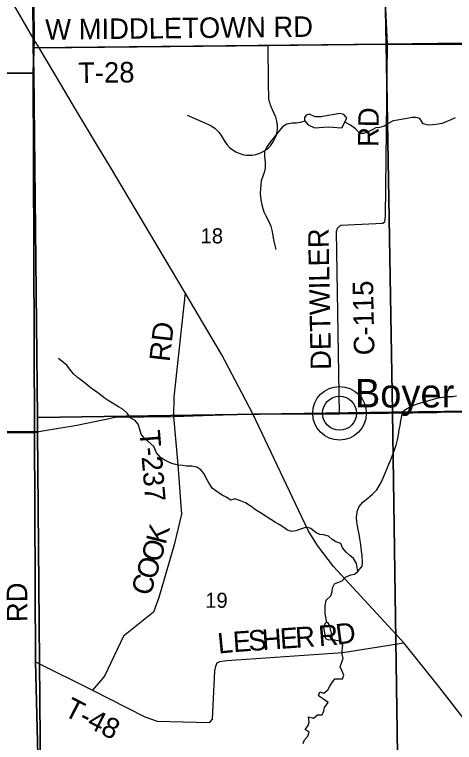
# Model space of a CAD drawing. Extents: x 0 to 36.9, y 0 to 22.
# Drawn here: x 4.166 to 5.386, y 16.582 to 18.601 of the extents above; entities that cross this region are included whole.
import ezdxf

# ---------------------------------------------------------------- set-up
doc = ezdxf.new("R2010")
doc.units = 0
for name, color, linetype in [('GM_X_County_Road', 7, 'Continuous'), ('GM_X_County_Road_Text', 7, 'Continuous'), ('GM_X_Minor_Lake', 7, 'Continuous'), ('GM_X_Minor_River', 7, 'Continuous'), ('GM_X_Rail_Line', 7, 'Continuous'), ('GM_X_Section', 7, 'Continuous'), ('GM_X_Section_Text', 7, 'Continuous'), ('GM_X_State_Route', 7, 'Continuous'), ('GM_X_Township_Road', 7, 'Continuous'), ('GM_X_Township_Road_Text', 7, 'Continuous'), ('GM_X_Unincorporated', 7, 'Continuous'), ('GM_X_Unincorporated_Location', 7, 'Continuous'), ('GM_X_Unincorporated_Text', 7, 'Continuous')]:
    doc.layers.add(name, color=color, linetype=linetype)

msp = doc.modelspace()

# ---------------------------------------------------------------- linework, layer by layer
at = {"layer": 'GM_X_County_Road'}
for points in [[(5.0673, 17.4931), (5.0594, 17.9986), (5.0622, 18.0085), (5.0708, 18.0163), (5.188, 18.0224), (5.1928, 18.0266), (5.1952, 18.0408), (5.2008, 18.5186), (5.1771, 19.01), (5.1803, 19.5234)], [(4.2216, 17.4415), (4.2176, 18.4377), (4.2202, 18.5304)], [(4.2488, 15.4651), (4.2434, 15.9526), (4.243, 16.0644), (4.2239, 16.8055), (4.2216, 17.4415)]]:
    msp.add_lwpolyline(points, dxfattribs=at)
at = {"layer": 'GM_X_Minor_Lake'}
for points in [[(5.0874, 18.3132), (5.0846, 18.3166), (5.0792, 18.3233), (5.0681, 18.3262), (5.0154, 18.3166), (4.9998, 18.3171), (4.9845, 18.324), (4.975, 18.3216), (4.9698, 18.3151), (4.9707, 18.3067), (4.9804, 18.2951), (4.9984, 18.2867), (5.036, 18.2896), (5.0741, 18.2864)], [(5.0741, 18.2864), (5.0874, 18.3132)], [(5.04, 16.9072), (5.0349, 16.9143), (5.0292, 16.9139), (5.027, 16.9112), (5.0229, 16.902), (5.0288, 16.8702), (5.0364, 16.8661), (5.0463, 16.8671), (5.0474, 16.8776)], [(5.0474, 16.8776), (5.04, 16.9072)]]:
    msp.add_lwpolyline(points, dxfattribs=at)
at = {"layer": 'GM_X_Minor_River'}
for points in [[(5.3881, 18.3144), (5.3745, 18.308), (5.3647, 18.3045), (5.3519, 18.2989), (5.336, 18.296), (5.3265, 18.295), (5.314, 18.2941), (5.2999, 18.2972), (5.2898, 18.3122), (5.2802, 18.3155), (5.2685, 18.3149), (5.2552, 18.3128), (5.2385, 18.3098), (5.2283, 18.3081), (5.2158, 18.3056), (5.2027, 18.2989)], [(4.9717, 18.3054), (4.9585, 18.301), (4.9479, 18.2997), (4.9357, 18.2991), (4.9217, 18.297), (4.9089, 18.2891), (4.8974, 18.2741), (4.887, 18.2618), (4.8748, 18.2464), (4.8655, 18.2337), (4.8597, 18.2211), (4.8591, 18.2066), (4.8613, 18.1903), (4.8609, 18.1744), (4.858, 18.163), (4.8544, 18.1523), (4.8505, 18.14), (4.8488, 18.1282), (4.8478, 18.1187), (4.8473, 18.1032), (4.8488, 18.0872), (4.8525, 18.0695), (4.8573, 18.0532), (4.8629, 18.0423), (4.8683, 18.0325), (4.8767, 18.0137), (4.8795, 18.0028), (4.8824, 17.988), (4.8842, 17.9759), (4.887, 17.9638), (4.8904, 17.949)], [(5.2027, 18.2989), (5.1925, 18.2915), (5.1782, 18.2878), (5.168, 18.2861), (5.1582, 18.281), (5.1446, 18.2747), (5.1341, 18.2707), (5.1234, 18.2709), (5.1122, 18.284), (5.0983, 18.2936), (5.0819, 18.3021)], [(5.1183, 17.0563), (5.1141, 17.0786), (5.1059, 17.0918), (5.0963, 17.1), (5.0862, 17.1097), (5.0758, 17.122), (5.0706, 17.1337), (5.0576, 17.138), (5.0469, 17.1446), (5.0368, 17.154), (5.0231, 17.1579), (5.0132, 17.1585), (5.0025, 17.1632), (4.9882, 17.1751), (4.9756, 17.1794), (4.959, 17.1738), (4.9458, 17.169), (4.9352, 17.167), (4.9234, 17.1709), (4.9103, 17.1802), (4.8999, 17.1868), (4.8899, 17.1923), (4.8765, 17.2005), (4.8642, 17.2086), (4.8481, 17.2186), (4.8339, 17.2274), (4.8219, 17.2363), (4.8062, 17.2463), (4.7928, 17.2521), (4.7771, 17.2579), (4.7658, 17.2543), (4.7527, 17.262), (4.7416, 17.2679), (4.7247, 17.2794), (4.7143, 17.2876), (4.7038, 17.3037), (4.6967, 17.3169), (4.692, 17.327), (4.6826, 17.3379), (4.6719, 17.3453), (4.6574, 17.3481), (4.6441, 17.3486), (4.6315, 17.3499), (4.6209, 17.3512), (4.6091, 17.3536), (4.5995, 17.3565), (4.5808, 17.3653), (4.5708, 17.3723), (4.5595, 17.385), (4.5524, 17.4024), (4.5358, 17.4177), (4.5262, 17.4247), (4.5172, 17.4371), (4.5135, 17.4499), (4.5084, 17.4642), (4.5002, 17.4751), (4.4887, 17.4814), (4.4786, 17.4952), (4.467, 17.5049), (4.4543, 17.5126), (4.4374, 17.523), (4.4255, 17.53), (4.4144, 17.5378), (4.404, 17.5463), (4.3928, 17.5545), (4.3832, 17.5611), (4.3736, 17.5682), (4.3624, 17.5775), (4.3504, 17.5871), (4.3408, 17.5942), (4.3293, 17.6042), (4.3215, 17.6147), (4.3106, 17.6285), (4.2979, 17.6386), (4.2882, 17.6464)], [(5.0322, 16.9141), (5.0278, 16.9393), (5.0274, 16.962), (5.0306, 16.9761), (5.0436, 16.9889), (5.0472, 16.9992), (5.0482, 17.011), (5.0533, 17.0221), (5.0631, 17.0257), (5.0748, 17.0301), (5.0837, 17.0405), (5.0988, 17.0465), (5.1086, 17.0485), (5.1183, 17.0563), (5.1299, 17.0709), (5.1316, 17.0805), (5.1301, 17.1002), (5.1287, 17.1127), (5.1274, 17.1225), (5.1253, 17.1362), (5.1235, 17.1471), (5.1218, 17.16), (5.1193, 17.1721), (5.1172, 17.1831), (5.1159, 17.1941), (5.1149, 17.2055), (5.1155, 17.215), (5.1172, 17.2249), (5.1219, 17.236), (5.1323, 17.2487), (5.1462, 17.2596), (5.1585, 17.2704), (5.1705, 17.2824), (5.1775, 17.2932), (5.1837, 17.3043), (5.1896, 17.318), (5.1943, 17.3288), (5.1986, 17.3402), (5.2041, 17.3536), (5.2088, 17.3643), (5.2147, 17.3785), (5.2194, 17.3911), (5.2248, 17.4068), (5.2279, 17.4212), (5.2307, 17.4353), (5.2331, 17.4487), (5.2356, 17.4605), (5.2376, 17.4738), (5.239, 17.4833), (5.2411, 17.4929), (5.2458, 17.5024), (5.2661, 17.5142), (5.2835, 17.521), (5.2933, 17.5238), (5.3277, 17.5343), (5.3409, 17.5379), (5.3541, 17.5397), (5.3682, 17.5411), (5.3822, 17.5417), (5.3921, 17.543)], [(4.9664, 16.579), (4.97, 16.5889), (4.9797, 16.5993), (4.9836, 16.61), (4.9721, 16.6174), (4.9807, 16.6286), (4.9835, 16.6393), (4.9817, 16.6533), (4.9951, 16.6497), (5.0067, 16.6587), (5.0196, 16.6585), (5.0243, 16.6692), (5.0257, 16.6791), (5.0357, 16.6926), (5.0226, 16.7019), (5.0095, 16.7115), (5.0128, 16.7222), (5.0238, 16.719), (5.0354, 16.7279), (5.0406, 16.7379), (5.0468, 16.7479), (5.0546, 16.7579), (5.0755, 16.7582), (5.0795, 16.7682), (5.0751, 16.7799), (5.0692, 16.7919), (5.0739, 16.8049), (5.0779, 16.8156), (5.0743, 16.8269), (5.0745, 16.838), (5.0769, 16.8513), (5.0698, 16.8626), (5.0576, 16.865), (5.0464, 16.8675)]]:
    msp.add_lwpolyline(points, dxfattribs=at)
at = {"layer": 'GM_X_Rail_Line'}
for points in [[(8.9, 14.5158), (8.9, 20.5927), (8.7004, 20.5894), (8.4791, 20.5781), (8.4706, 20.5777), (8.1451, 20.581), (7.7514, 20.5725), (7.4889, 20.5693), (7.1656, 20.5637), (7.1468, 20.5633), (6.1727, 20.5478), (5.9236, 20.5446), (5.3186, 20.5329), (5.2978, 20.5324), (5.1496, 20.5295), (4.5929, 20.5183), (4.1742, 20.5119), (4.2095, 19.5156), (4.2124, 19.4314), (4.22, 18.531), (4.2174, 18.4382), (4.2214, 17.442), (4.2237, 16.806), (4.2428, 16.065)], [(4.2428, 16.065), (4.2237, 16.806), (4.2214, 17.442), (4.2174, 18.4382), (4.22, 18.531), (4.2124, 19.4314), (4.2095, 19.5156), (4.1742, 20.5119), (3.4355, 20.4995), (3.1942, 20.4953), (2.6054, 20.4898), (2.1, 20.4802), (2.1, 14.4405)]]:
    msp.add_lwpolyline(points, dxfattribs=at)
at = {"layer": 'GM_X_Section'}
for points in [[(6.1867, 19.5319), (6.2072, 18.5313), (5.197, 18.519), (5.1777, 19.5195)], [(5.1777, 19.5195), (5.197, 18.519), (4.2176, 18.508), (4.212, 19.4289), (4.2133, 19.5112)], [(4.212, 19.4289), (4.2176, 18.508), (4.219, 18.4391), (3.226, 18.4277), (3.2188, 19.419)], [(4.2176, 18.508), (5.197, 18.519), (5.2141, 17.498), (4.2298, 17.4831), (4.219, 18.4391)], [(5.197, 18.519), (6.2072, 18.5313), (6.2201, 17.5106), (5.2141, 17.498)], [(4.219, 18.4391), (4.2298, 17.4831), (4.2298, 17.4444), (3.2373, 17.4365), (3.226, 18.4277)], [(6.2201, 17.5106), (6.226, 16.4996), (5.2292, 16.4845), (5.2141, 17.498)], [(5.2141, 17.498), (5.2292, 16.4845), (4.2381, 16.4858), (4.2298, 17.4444), (4.2298, 17.4831)], [(4.2298, 17.4444), (4.2381, 16.4858), (4.2388, 16.4513), (3.2483, 16.4396), (3.2373, 17.4365)]]:
    msp.add_lwpolyline(points, close=True, dxfattribs=at)
at = {"layer": 'GM_X_State_Route'}
for p, q in [((4.234, 18.5081), (4.2202, 18.5304)), ((4.2949, 18.4062), (4.234, 18.5081)), ((4.3354, 18.3383), (4.2949, 18.4062)), ((4.3658, 18.2874), (4.3354, 18.3383)), ((4.3962, 18.2364), (4.3658, 18.2874)), ((4.4317, 18.177), (4.3962, 18.2364))]:
    msp.add_line(p, q, dxfattribs=at)
for points in [[(4.2202, 18.5304), (4.0532, 18.8191), (4.0295, 18.8744), (3.802, 19.4268)], [(5.504, 16.4959), (5.45, 16.5871), (5.4199, 16.6383), (5.3454, 16.7333), (5.2454, 16.8581), (5.0508, 17.0699), (5.0061, 17.1277), (4.9804, 17.1698), (4.8265, 17.4934), (4.741, 17.6571), (4.6391, 17.8287), (4.4642, 18.1227), (4.4317, 18.177)], [(4.2216, 17.4415), (4.243, 17.446), (4.334, 17.4611), (4.4155, 17.4778), (4.4453, 17.4838), (4.6071, 17.4861), (4.8265, 17.4934)], [(4.8265, 17.4934), (5.0673, 17.4931), (5.3373, 17.4973), (5.3473, 17.4975)], [(5.3473, 17.4975), (5.4944, 17.4998), (5.5025, 17.4999), (5.5148, 17.5001), (5.6182, 17.5016), (5.6272, 17.5017)], [(2.4919, 17.4281), (3.2285, 17.4352), (4.2216, 17.4415)]]:
    msp.add_lwpolyline(points, dxfattribs=at)
at = {"layer": 'GM_X_Township_Road'}
msp.add_line((5.2008, 18.5186), (5.5124, 18.5192), dxfattribs=at)
for points in [[(4.234, 18.5081), (4.8692, 18.5153), (5.2008, 18.5186)], [(4.6446, 18.3215), (4.6726, 18.3093), (4.6952, 18.2997), (4.7035, 18.2961), (4.7111, 18.2923), (4.7163, 18.2891), (4.722, 18.285), (4.7263, 18.2812), (4.7323, 18.2746), (4.7388, 18.2652), (4.7471, 18.2515), (4.7548, 18.2403), (4.7618, 18.2324), (4.7696, 18.226), (4.7794, 18.2196), (4.7879, 18.2159), (4.802, 18.2117), (4.8097, 18.2109), (4.8151, 18.2107), (4.8251, 18.2109), (4.8356, 18.2126), (4.8465, 18.2163), (4.8559, 18.2209), (4.8627, 18.2253), (4.8702, 18.2312), (4.8757, 18.2368), (4.8837, 18.2474), (4.8884, 18.2567), (4.8924, 18.2671), (4.8944, 18.2766), (4.8952, 18.284), (4.8955, 18.2933), (4.8939, 18.3053), (4.8905, 18.3164), (4.8815, 18.3364), (4.8764, 18.3496), (4.8739, 18.3564), (4.8718, 18.3619), (4.8711, 18.366), (4.8705, 18.4122), (4.8692, 18.5153)], [(2.1, 18.4182), (3.2275, 18.4294), (3.5067, 18.4318), (4.2176, 18.4377)], [(4.6391, 17.8287), (4.6073, 17.5395), (4.6071, 17.4861), (4.6189, 17.3516), (4.6258, 17.2514), (4.6293, 17.2146), (4.6088, 17.1301), (4.5658, 16.9842), (4.5511, 16.9432), (4.4681, 16.8764), (4.4151, 16.7653), (4.3819, 16.7269)], [(4.2239, 16.8055), (4.3819, 16.7269), (4.5274, 16.653), (4.5615, 16.6412), (4.7056, 16.6368), (4.7097, 16.6399), (4.7149, 16.6469), (4.7213, 16.7809), (4.7244, 16.7935), (4.728, 16.8023), (4.7352, 16.8063), (4.7545, 16.809), (5.0769, 16.831), (5.2454, 16.8581)]]:
    msp.add_lwpolyline(points, dxfattribs=at)
at = {"layer": 'GM_X_Unincorporated'}
for radius in [0.0744, 0.0472]:
    msp.add_circle((5.0674, 17.4948), radius, dxfattribs=at)
at = {"layer": 'GM_X_Unincorporated_Location'}
msp.add_line((5.0674, 17.4948), (5.0674, 17.4948), dxfattribs=at)

# ---------------------------------------------------------------- texts
at = {"layer": 'GM_X_County_Road_Text'}
for s, rotation, p in [('RD', 89.0128, (5.175, 18.2331)), ('DETWILER', 91.0758, (5.0442, 17.6157)), ('C-115', 91.1022, (5.1644, 17.6563)), ('RD', 90.4937, (4.2017, 16.9159))]:
    msp.add_text(s, height=0.05682, rotation=rotation, dxfattribs=at).set_placement(p)
at = {"layer": 'GM_X_Section_Text'}
for s, p in [('18', (4.682, 17.9661)), ('19', (4.6949, 16.9553))]:
    msp.add_text(s, height=0.04186, rotation=0, dxfattribs=at).set_placement(p)
at = {"layer": 'GM_X_Township_Road_Text'}
for s, height, rotation, p in [('W MIDDLETOWN RD', 0.056818, 0.6364, (4.2513, 18.5309)), ('T-28', 0.05682, 0.7069, (4.3427, 18.4108)), ('RD', 0.05682, 83.5521, (4.596, 17.6361)), ('T-237', 0.05682, 274.7182, (4.5124, 17.4455)), ('K', 0.0568, 75.5772, (4.5849, 17.1287)), ('O', 0.0568, 73.7503, (4.5704, 17.0788)), ('O', 0.0568, 73.3887, (4.556, 17.0305)), ('C', 0.0568, 73.3877, (4.5426, 16.9858)), ('H', 0.0568, 4.0029, (4.8542, 16.838)), ('E', 0.0568, 4.0016, (4.9041, 16.8414)), ('R', 0.0568, 4, (4.9465, 16.8444)), ('R', 0.0568, 4.4389, (5.011, 16.8489)), ('D', 0.0568, 7.6442, (5.061, 16.8529)), ('L', 0.0568, 5.4637, (4.7317, 16.8282)), ('E', 0.0568, 4.0942, (4.7736, 16.8322)), ('S', 0.0568, 4.0017, (4.816, 16.8353)), ('T-48', 0.05682, 333.2772, (4.2997, 16.658))]:
    msp.add_text(s, height=height, rotation=rotation, dxfattribs=at).set_placement(p)
at = {"layer": 'GM_X_Unincorporated_Text'}
msp.add_text('Boyer', height=0.07898, rotation=0, dxfattribs=at).set_placement((5.1099, 17.511))

doc.saveas('drawing.dxf')
